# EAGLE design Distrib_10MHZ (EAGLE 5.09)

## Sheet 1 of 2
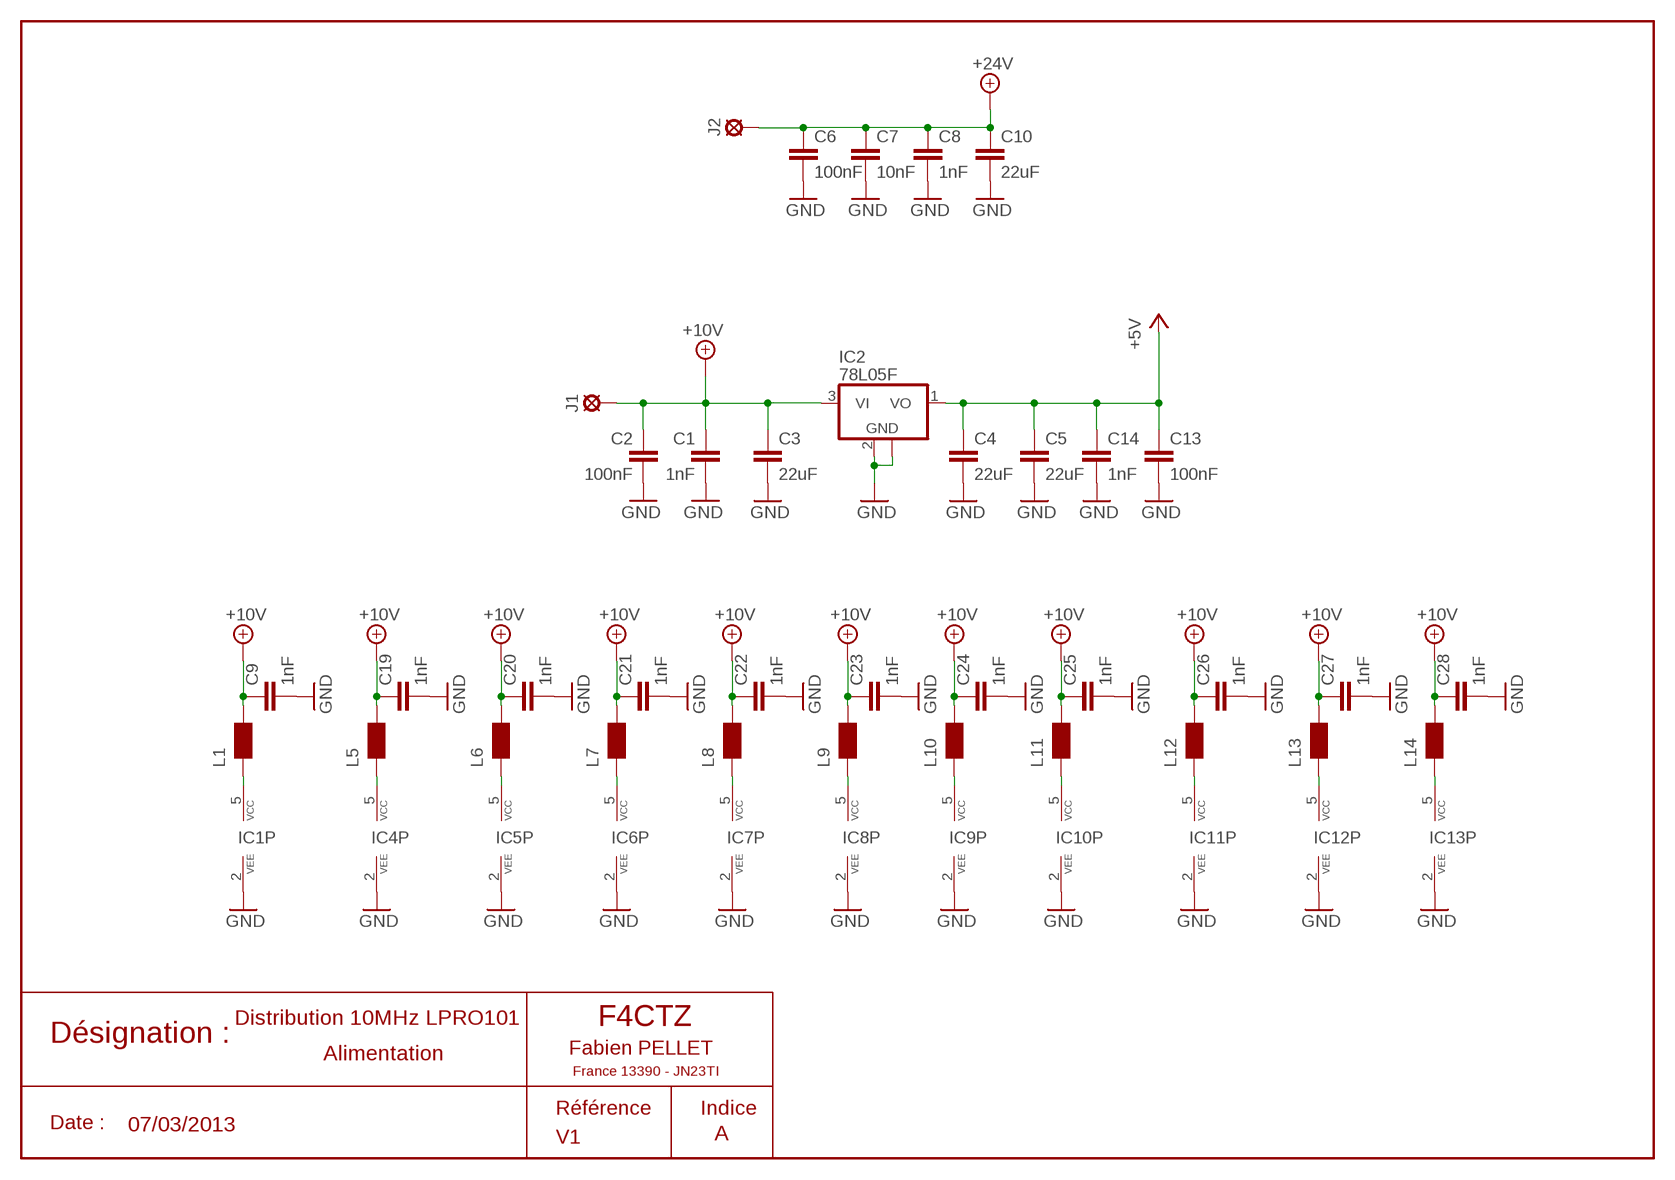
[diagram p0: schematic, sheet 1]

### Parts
C1  1nF  C-EUC0603  [C0603]
C2  100nF  C-EUC0603  [C0603]
C3  22uF  C-EUC1210  [C1210]
C4  22uF  C-EUC1210  [C1210]
C5  22uF  C-EUC1210  [C1210]
C6  100nF  C-EUC0603  [C0603]
C7  10nF  C-EUC0603  [C0603]
C8  1nF  C-EUC0603  [C0603]
C9  1nF  C-EUC0603  [C0603]
C10  22uF  C-EUC1210  [C1210]
C13  100nF  C-EUC0603  [C0603]
C14  1nF  C-EUC0603  [C0603]
C19  1nF  C-EUC0603  [C0603]
C20  1nF  C-EUC0603  [C0603]
C21  1nF  C-EUC0603  [C0603]
C22  1nF  C-EUC0603  [C0603]
C23  1nF  C-EUC0603  [C0603]
C24  1nF  C-EUC0603  [C0603]
C25  1nF  C-EUC0603  [C0603]
C26  1nF  C-EUC0603  [C0603]
C27  1nF  C-EUC0603  [C0603]
C28  1nF  C-EUC0603  [C0603]
IC1  MAX4390  MAX4105EUK  [SOT23-5L]
IC2  78L05F  [SOT89]
IC4  MAX4390  MAX4105EUK  [SOT23-5L]
IC5  MAX4390  MAX4105EUK  [SOT23-5L]
IC6  MAX4390  MAX4105EUK  [SOT23-5L]
IC7  MAX4390  MAX4105EUK  [SOT23-5L]
IC8  MAX4390  MAX4105EUK  [SOT23-5L]
IC9  MAX4390  MAX4105EUK  [SOT23-5L]
IC10  MAX4390  MAX4105EUK  [SOT23-5L]
IC11  MAX4390  MAX4105EUK  [SOT23-5L]
IC12  MAX4390  MAX4105EUK  [SOT23-5L]
IC13  MAX4390  MAX4105EUK  [SOT23-5L]
J1  +10V  SE14  [SE14]
J2  +24V  SE14  [SE14]
L1  WE-KIHC_0603  [WE-KI_0603_B]
L5  WE-KIHC_0603  [WE-KI_0603_B]
L6  WE-KIHC_0603  [WE-KI_0603_B]
L7  WE-KIHC_0603  [WE-KI_0603_B]
L8  WE-KIHC_0603  [WE-KI_0603_B]
L9  WE-KIHC_0603  [WE-KI_0603_B]
L10  WE-KIHC_0603  [WE-KI_0603_B]
L11  WE-KIHC_0603  [WE-KI_0603_B]
L12  WE-KIHC_0603  [WE-KI_0603_B]
L13  WE-KIHC_0603  [WE-KI_0603_B]
L14  WE-KIHC_0603  [WE-KI_0603_B]

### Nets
+5V: C4.1 C5.1 C13.1 C14.1 IC2.1(VO) ; also sheet 2
+10V [Alim]: C1.1 C2.1 C3.1 C9.1 C19.1 C20.1 C21.1 C22.1 C23.1 C24.1 C25.1 C26.1 C27.1 C28.1 IC2.3(VI) J1.MP L1.1 L5.1 L6.1 L7.1 L8.1 L9.1 L10.1 L11.1 L12.1 L13.1 L14.1 ; also sheet 2
+24V: C6.1 C7.1 C8.1 C10.1 J2.MP ; also sheet 2
GND [Alim]: C1.2 C2.2 C3.2 C4.2 C5.2 C6.2 C7.2 C8.2 C9.2 C10.2 C13.2 C14.2 C19.2 C20.2 C21.2 C22.2 C23.2 C24.2 C25.2 C26.2 C27.2 C28.2 IC1.2(VEE) IC2.2(GND) IC2.2@1(GND) IC4.2(VEE) IC5.2(VEE) IC6.2(VEE) IC7.2(VEE) IC8.2(VEE) IC9.2(VEE) IC10.2(VEE) IC11.2(VEE) IC12.2(VEE) IC13.2(VEE) ; also sheet 2
N$5: IC1.5(VCC) L1.2
N$15: IC4.5(VCC) L5.2
N$17: IC5.5(VCC) L6.2
N$18: IC6.5(VCC) L7.2
N$19: IC7.5(VCC) L8.2
N$20: IC8.5(VCC) L9.2
N$21: IC9.5(VCC) L10.2
N$22: IC10.5(VCC) L11.2
N$23: IC11.5(VCC) L12.2
N$24: IC12.5(VCC) L13.2
N$25: IC13.5(VCC) L14.2

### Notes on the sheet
- Distribution 10MHz LPRO101
- Alimentation
- 07/03/2013
- A

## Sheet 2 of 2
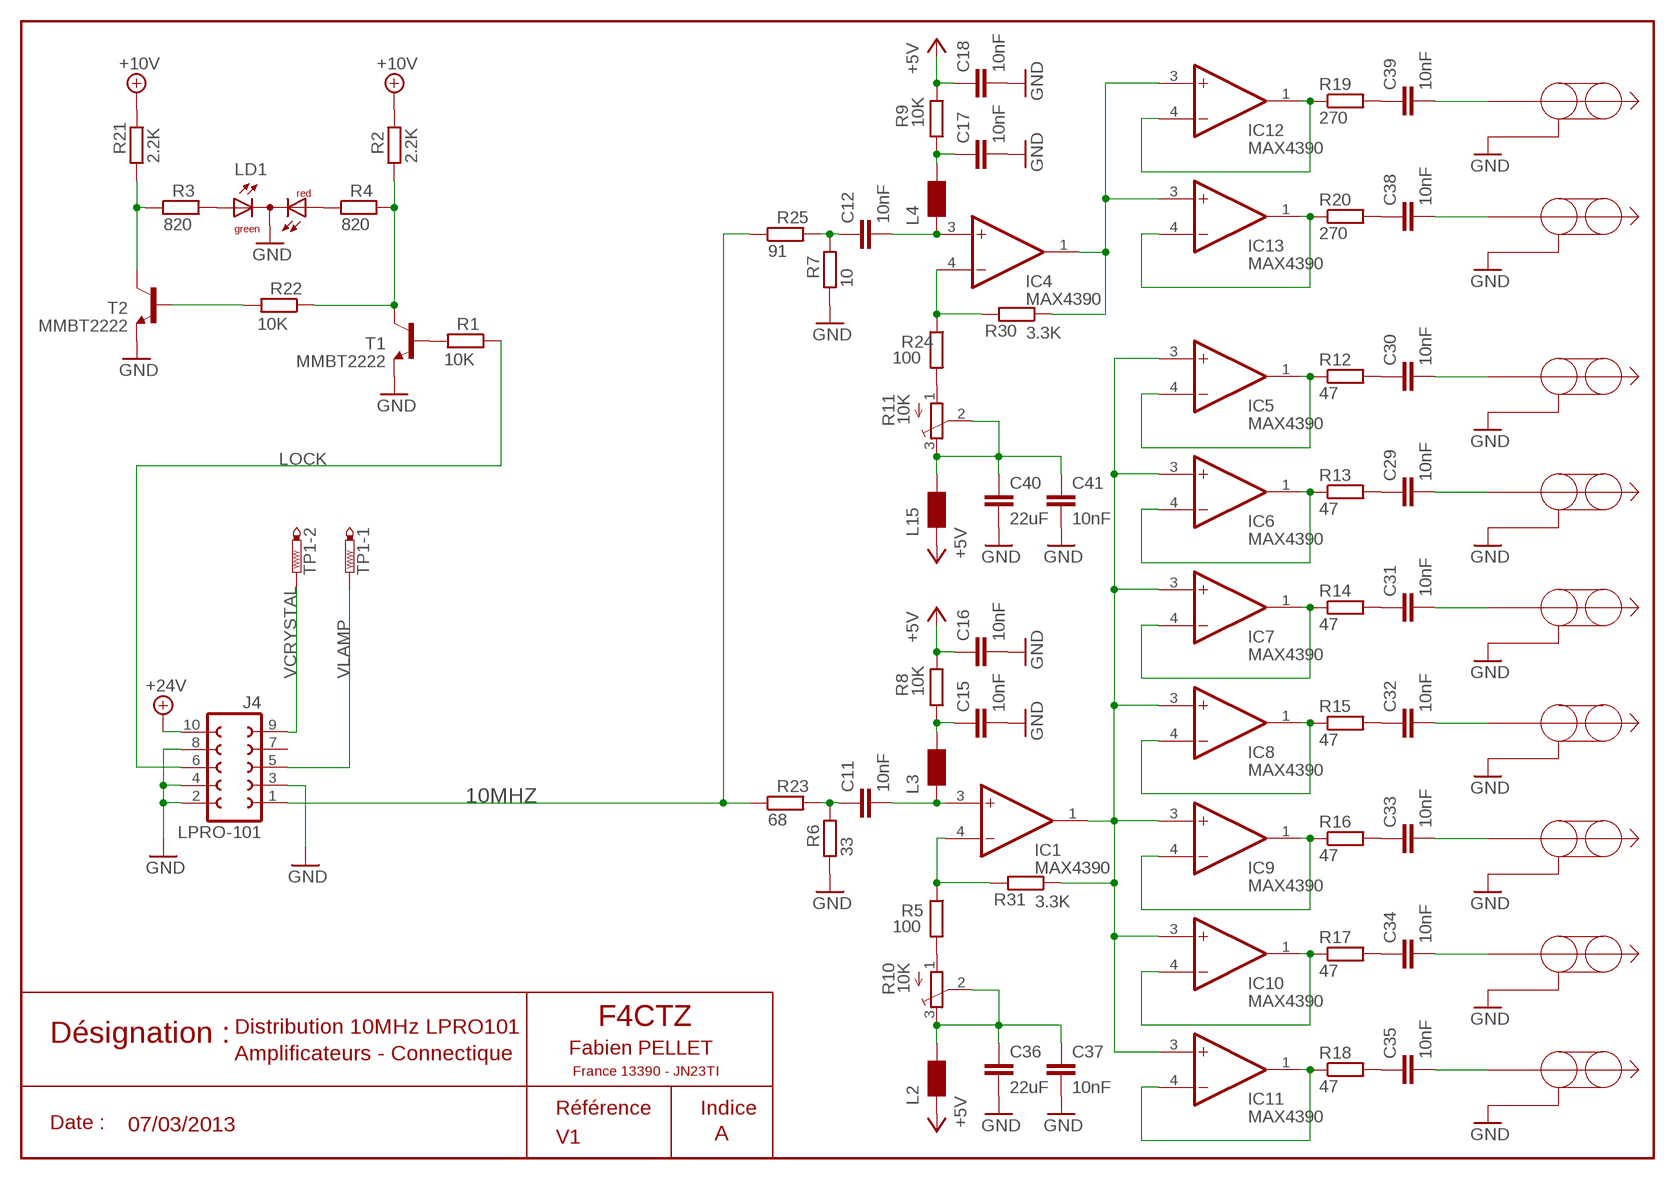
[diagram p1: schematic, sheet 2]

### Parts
C11  10nF  C-EUC0603  [C0603]
C12  10nF  C-EUC0603  [C0603]
C15  10nF  C-EUC0603  [C0603]
C16  10nF  C-EUC0603  [C0603]
C17  10nF  C-EUC0603  [C0603]
C18  10nF  C-EUC0603  [C0603]
C29  10nF  C-EUC0603  [C0603]
C30  10nF  C-EUC0603  [C0603]
C31  10nF  C-EUC0603  [C0603]
C32  10nF  C-EUC0603  [C0603]
C33  10nF  C-EUC0603  [C0603]
C34  10nF  C-EUC0603  [C0603]
C35  10nF  C-EUC0603  [C0603]
C36  22uF  C-EUC1210  [C1210]
C37  10nF  C-EUC0603  [C0603]
C38  10nF  C-EUC0603  [C0603]
C39  10nF  C-EUC0603  [C0603]
C40  22uF  C-EUC1210  [C1210]
C41  10nF  C-EUC0603  [C0603]
J4  LPRO-101  FE05-2  [FE05-2]
J5  ANT'  [ANT]
J6  ANT'  [ANT]
J7  ANT'  [ANT]
J8  ANT'  [ANT]
J9  ANT'  [ANT]
J10  ANT'  [ANT]
J11  ANT'  [ANT]
J12  ANT'  [ANT]
J13  ANT'  [ANT]
L2  WE-KIHC_0603  [WE-KI_0603_B]
L3  WE-KIHC_0603  [WE-KI_0603_B]
L4  WE-KIHC_0603  [WE-KI_0603_B]
L15  WE-KIHC_0603  [WE-KI_0603_B]
LD1  DUOLED-RG-C  [DUOLED-C-5MM]
R1  10K  R-EU_R0603  [R0603]
R2  2.2K  R-EU_R0603  [R0603]
R3  820  R-EU_R0603  [R0603]
R4  820  R-EU_R0603  [R0603]
R5  100  R-EU_R0603  [R0603]
R6  33  R-EU_R0603  [R0603]
R7  10  R-EU_R0603  [R0603]
R8  10K  R-EU_R0603  [R0603]
R9  10K  R-EU_R0603  [R0603]
R10  10K  TRIM_EU-SM-42/43W  [SM-42/43W]
R11  10K  TRIM_EU-SM-42/43W  [SM-42/43W]
R12  47  R-EU_R0603  [R0603]
R13  47  R-EU_R0603  [R0603]
R14  47  R-EU_R0603  [R0603]
R15  47  R-EU_R0603  [R0603]
R16  47  R-EU_R0603  [R0603]
R17  47  R-EU_R0603  [R0603]
R18  47  R-EU_R0603  [R0603]
R19  270  R-EU_R0603  [R0603]
R20  270  R-EU_R0603  [R0603]
R21  2.2K  R-EU_R0603  [R0603]
R22  10K  R-EU_R0603  [R0603]
R23  68  R-EU_R0603  [R0603]
R24  100  R-EU_R0603  [R0603]
R25  91  R-EU_R0603  [R0603]
R30  3.3K  R-EU_R0603  [R0603]
R31  3.3K  R-EU_R0603  [R0603]
T1  MMBT2222  MMBT2222ALT1-NPN-SOT23-BEC  [SOT23-BEC]
T2  MMBT2222  MMBT2222ALT1-NPN-SOT23-BEC  [SOT23-BEC]
TP1  PTR2  [P2-38-17]

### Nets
10MHZ [RF]: J4.1 R23.1 R25.1
+5V: C16.1 C18.1 L2.2 L15.2 R8.2 R9.2 ; also sheet 1
+10V [Alim]: R2.2 R21.2 ; also sheet 1
+24V: J4.10 ; also sheet 1
GND [Alim]: C15.2 C16.2 C17.2 C18.2 C36.2 C37.2 C40.2 C41.2 J4.2 J4.3 J4.4 J4.8 J5.P$2 J6.P$2 J7.P$2 J8.P$2 J9.P$2 J10.P$2 J11.P$2 J12.P$2 J13.P$2 LD1.C R6.1 R7.1 T1.E T2.E ; also sheet 1
LOCK: J4.6 R1.1
N$2: R2.1 R4.2 R22.1 T1.C
N$3: R1.2 T1.B
N$4: C15.1 L3.1 R8.1
N$6: R3.1 R21.1 T2.C
N$7: R22.2 T2.B
N$9: IC5.1(OUT) IC5.4(-IN) R12.1
N$10: C11.2 IC1.3(+IN) L3.2
N$11: C17.1 L4.1 R9.1
N$12: C12.2 IC4.3(+IN) L4.2
N$13: IC1.4(-IN) R5.1 R31.2
N$14 [RFOUT]: C30.2 J7.P$1
N$16 [RFOUT]: C29.2 J8.P$1
N$26: IC6.1(OUT) IC6.4(-IN) R13.1
N$27 [RFOUT]: C31.2 J9.P$1
N$28: IC7.1(OUT) IC7.4(-IN) R14.1
N$29 [RFOUT]: C32.2 J10.P$1
N$30: IC8.1(OUT) IC8.4(-IN) R15.1
N$31 [RFOUT]: C33.2 J11.P$1
N$32: IC9.1(OUT) IC9.4(-IN) R16.1
N$33 [RFOUT]: C34.2 J12.P$1
N$34: IC10.1(OUT) IC10.4(-IN) R17.1
N$35 [RFOUT]: C35.2 J13.P$1
N$36: IC11.1(OUT) IC11.4(-IN) R18.1
N$37 [RFOUT]: C39.2 J5.P$1
N$38: IC12.1(OUT) IC12.4(-IN) R19.1
N$39 [RFOUT]: C38.2 J6.P$1
N$40: IC13.1(OUT) IC13.4(-IN) R20.1
N$41: LD1.AX(AG) R3.2
N$42: IC4.1(OUT) IC12.3(+IN) IC13.3(+IN) R30.1
N$43: IC1.1(OUT) IC5.3(+IN) IC6.3(+IN) IC7.3(+IN) IC8.3(+IN) IC9.3(+IN) IC10.3(+IN) IC11.3(+IN) R31.1
N$44: LD1.AR R4.1
N$45: IC4.4(-IN) R24.1 R30.2
N$46: C12.1 R7.2 R25.2
N$47: C29.1 R13.2
N$48: C30.1 R12.2
N$49: C31.1 R14.2
N$50: C32.1 R15.2
N$51: C33.1 R16.2
N$52: C34.1 R17.2
N$53: C35.1 R18.2
N$54: C36.1 C37.1 L2.1 R10.2(S) R10.3(E)
N$55: R5.2 R10.1(A)
N$56: C39.1 R19.2
N$57: C38.1 R20.2
N$58: C40.1 C41.1 L15.1 R11.2(S) R11.3(E)
N$59: R11.1(A) R24.2
N$60: C11.1 R6.2 R23.2
VCRYSTAL: J4.9 TP1.TP-2
VLAMP: J4.5 TP1.TP-1
Unconnected: J4.7

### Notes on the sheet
- Distribution 10MHz LPRO101
- Amplificateurs - Connectique
- 07/03/2013
- A

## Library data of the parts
C1-C41 = rcl:C-EU: CAPACITOR, European symbol
IC1 IC4-IC13 = maxim:MAX4105EUK: OP AMP
IC2 = linear:78L*: POSITOIV-VOLTAGE REGULATORS Output up to 100 mA Source: http://focus.ti.com/lit/ds/symlink/ua78l05.pdf
J1 J2 = solpad:SE14: SOLDER PAD
J4 = con-lsta:FE05-2: FEMALE HEADER
J5-J13 = fabien:ANT
L1-L15 = wuerth-elektronik:WE-KIHC: SMD Wire Wound Ceramic Inductor WE-KIHC
LD1 = led:DUOLED-RG-C: DUO LED 2 colors (red/green), 5 mm, round, common Cathode www.ligitek.com or other producers.
R1-R9 R12-R25 R30 R31 = rcl:R-EU_: RESISTOR, European symbol
R10 R11 = pot:TRIM_EU-: POTENTIOMETER
T1 T2 = transistor-neu-to92:*-NPN-: NPN Transistror
TP1 = testpad:PTR2: TEST PIN

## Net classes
1 Alim: clearance 0.4 mm to class 0, clearance 0.4 mm
2 RF: clearance 1.5 mm to class 0, clearance 1.5 mm to class 1, clearance 1.5 mm
3 RFOUT: clearance 1 mm to class 0, clearance 1 mm to class 1, clearance 1 mm to class 2, clearance 1 mm

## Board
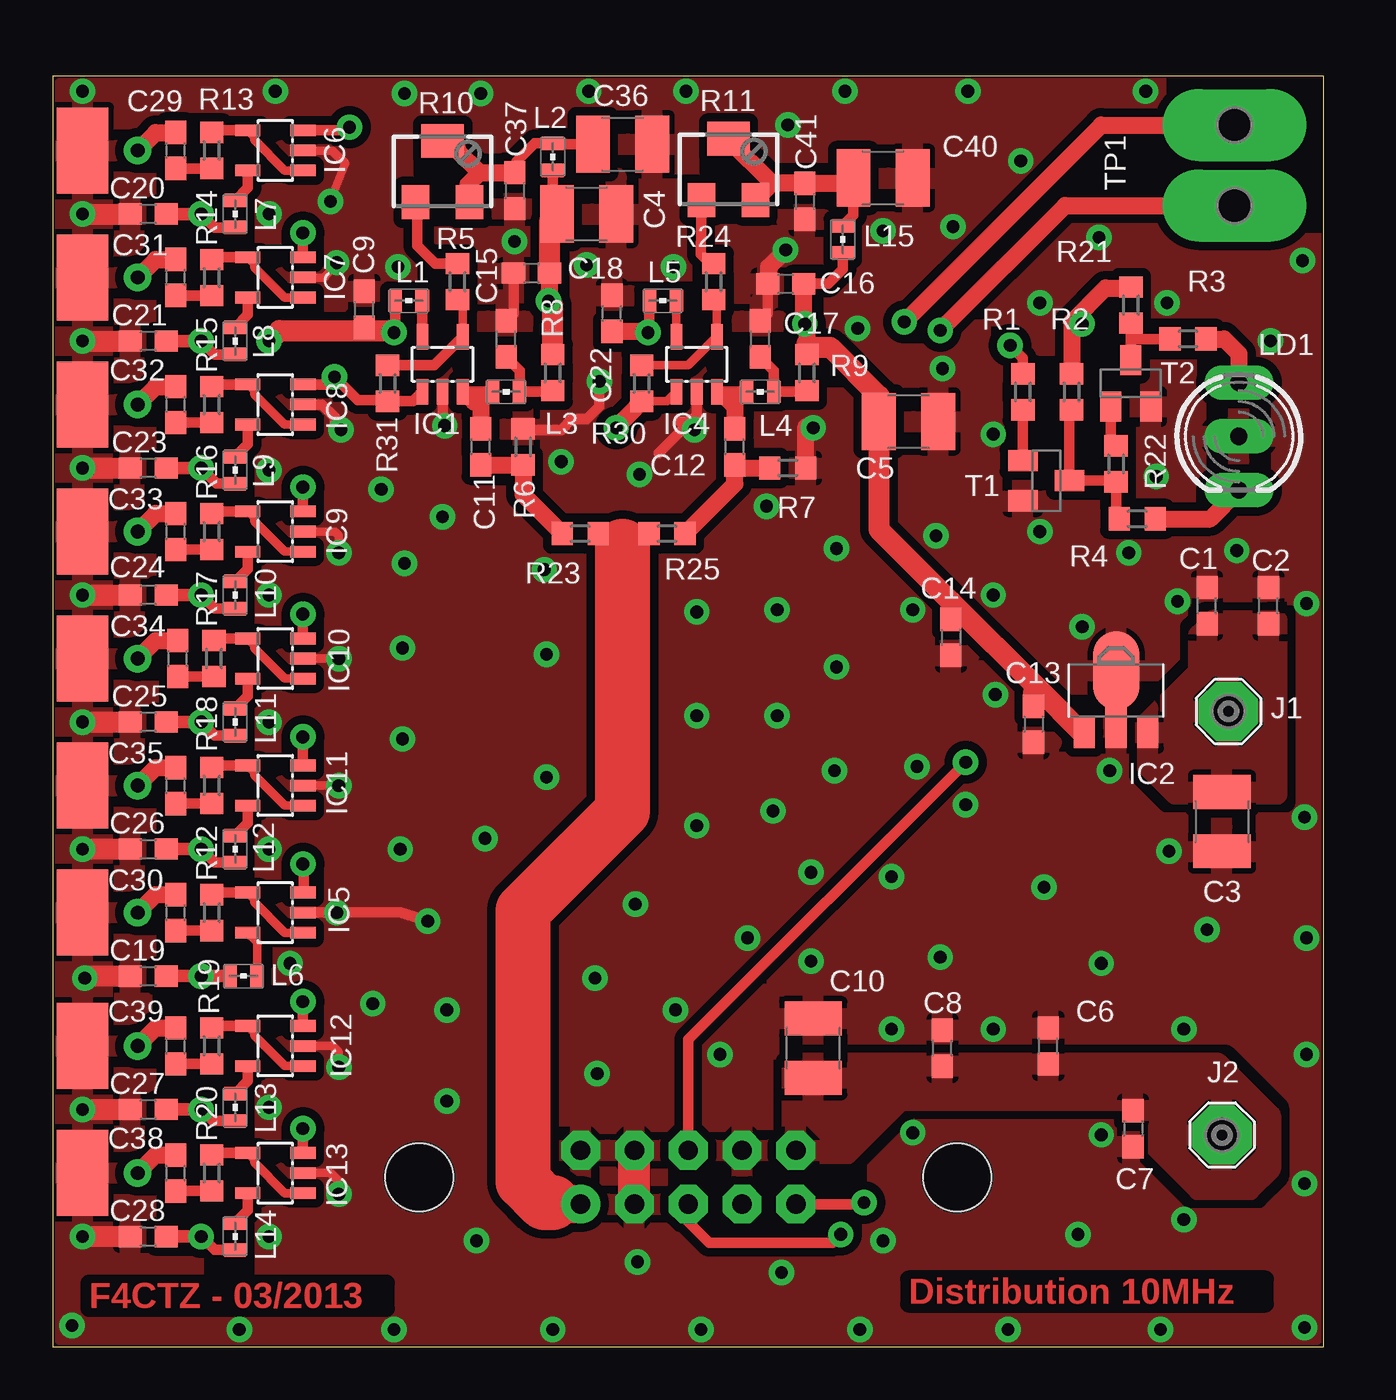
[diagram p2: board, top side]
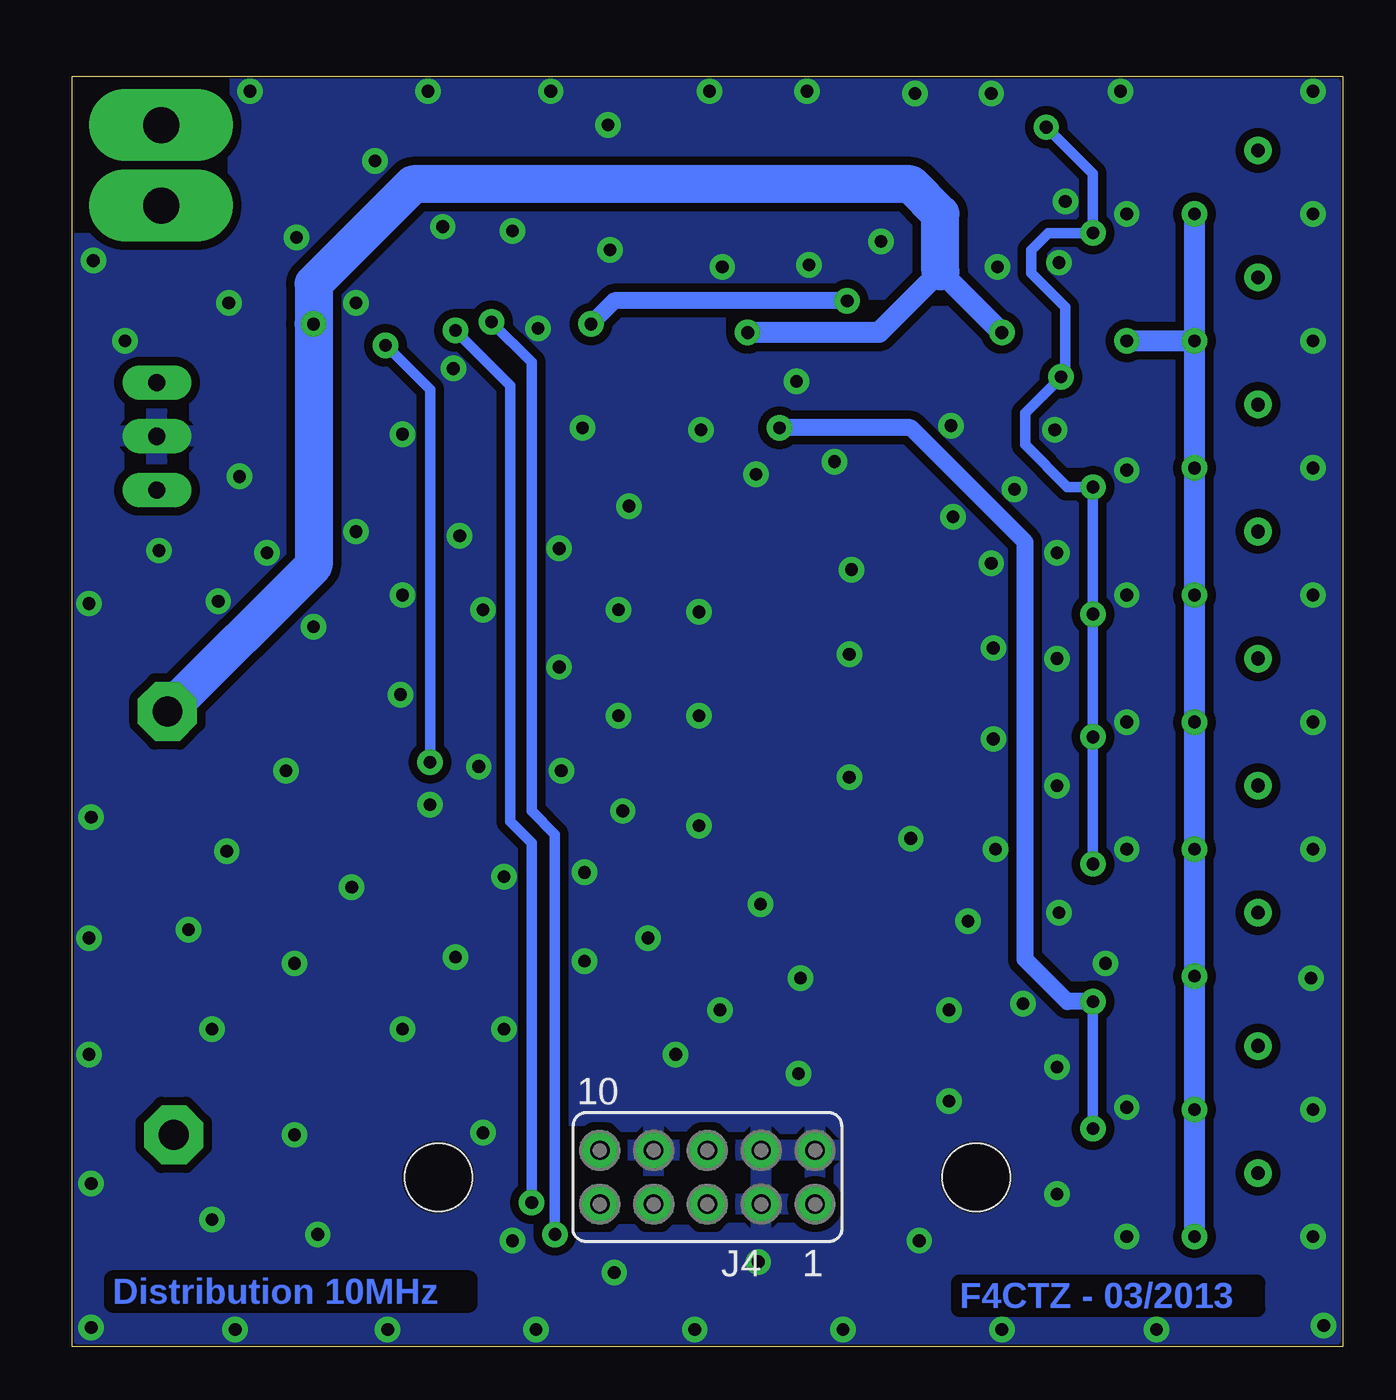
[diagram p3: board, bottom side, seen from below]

Size 60 x 60 mm. Coordinates in mm from the lower left corner, seen from the top.
Outline: 0,0 60,0 60,60 0,60 0,0
Copper layers (1*16): Top 0.035mm / dielectric 1.53mm / Bottom 0.035mm
Design rules "fabien *": minimum track width 0.21mm, minimum drill 0.5mm, track to track 0.21mm, track to pad 0.21mm, pad to pad 0.21mm, via to via 0.21mm, smd to smd 0.21mm, copper to edge 0.1mm, drill to drill 8mil, minimum pad ring 0.2mm, minimum via ring 0.2mm, stop-mask expansion 4mil, vias tented up to drill 0mil, thermal gap 10mil
Holes 3.2 mm at 17.3,8 42.7,8

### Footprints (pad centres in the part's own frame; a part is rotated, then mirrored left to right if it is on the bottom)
C0603 = smd 1.1 x 1: 1 -0.85,0; 2 0.85,0
C1210 = smd 1.6 x 2.7: 1 -1.4,0; 2 1.4,0
SOT23-5L = smd 0.55 x 1.2: 1 -0.95,-1.3; 2 0,-1.3; 3 0.95,-1.3; 4 0.95,1.3; 5 -0.95,1.3
SOT89 = smd 1 x 1.5: 1 -1.499,-1.981; 3 1.499,-1.981 | smd 1 x 2: 2 0,-1.727 | smd 2.2 x 3.7: 2@1 0,0.94
SE14 = drill 1.397 pad 2.54 octagon: MP 0,0
FE05-2 = drill 0.914 round: 1 -5.08,1.27 | drill 0.914 octagon: 2 -5.08,-1.27; 3 -2.54,1.27; 4 -2.54,-1.27; 5 0,1.27; 6 0,-1.27; 7 2.54,1.27; 8 2.54,-1.27; 9 5.08,1.27; 10 5.08,-1.27
ANT = drill 0.65 pad 1.032 round: P$1 0,0 | smd 4.064 x 2.438: P$2 0,-2.601
WE-KI_0603_B = smd 0.64 x 1.02: 1 -0.64,0; 2 0.64,0
DUOLED-C-5MM = drill 0.813 long: AR 2.54,0; AX -2.54,0; C 0,0
R0603 = smd 1 x 1.1: 1 -0.85,0; 2 0.85,0
SM-42/43W = smd 1.3 x 1.6: 1 -1.27,-1.45; 3 1.27,-1.45 | smd 2 x 1.6: 2 0,1.45
SOT23-BEC = smd 1 x 1.4: B -0.95,-1.1; C 0,1.1; E 0.95,-1.1
P2-38-17 = drill 1.702 pad 2.121 long: TP-1 -1.905,0; TP-2 1.905,0

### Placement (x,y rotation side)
C1  54.5,35 90 top
C2  57.4,35 90 top
C3  55.2,24.8 270 top
C4  25.2,53.5 0 top
C5  40.4,43.7 0 top
C6  47,14.2 90 top
C7  51,10.3 270 top
C8  42,14.1 90 top
C9  14.7,49 90 top
C10  35.9,14.1 90 top
C11  20.2,42.5 90 top
C12  32.2,42.5 90 top
C13  46.3,29.4 270 top
C14  42.4,33.5 270 top
C15  21.4,47.6 90 top
C16  34.6,50.2 180 top
C17  33.4,47.6 90 top
C18  22.6,50.7 180 top
C19  4.5,17.5 180 top
C20  4.5,53.5 180 top
C21  4.5,47.5 180 top
C22  26.4,48.8 90 top
C23  4.5,41.5 180 top
C24  4.5,35.5 180 top
C25  4.5,29.5 180 top
C26  4.5,23.5 180 top
C27  4.5,11.2 180 top
C28  4.5,5.2 180 top
C29  5.8,56.5 90 top
C30  5.8,20.5 90 top
C31  5.8,50.5 90 top
C32  5.8,44.5 90 top
C33  5.8,38.5 90 top
C34  5.9,32.5 90 top
C35  5.8,26.5 90 top
C36  26.9,56.8 0 top
C37  21.8,54.6 270 top
C38  5.8,8.2 90 top
C39  5.8,14.2 90 top
C40  39.2,55.2 0 top
C41  35.5,54.1 270 top
IC1  18.4,46.4 0 top
IC2  50.2,31 0 top
IC4  30.4,46.4 0 top
IC5  10.5,20.5 90 top
IC6  10.5,56.5 90 top
IC7  10.5,50.5 90 top
IC8  10.5,44.5 90 top
IC9  10.5,38.5 90 top
IC10  10.5,32.5 90 top
IC11  10.5,26.5 90 top
IC12  10.5,14.2 90 top
IC13  10.5,8.2 90 top
J1  55.5,30 0 top
J2  55.2,10 0 top
J4  30,8 180 bottom
J5  4,14.2 270 top
J6  4,8.2 270 top
J7  4,20.5 270 top
J8  4,56.5 270 top
J9  4,50.5 270 top
J10  4,44.5 270 top
J11  4,38.5 270 top
J12  4,32.5 270 top
J13  4,26.5 270 top
L1  16.8,49.4 0 top
L2  23.6,56.2 270 top
L3  21.4,45.1 180 top
L4  33.4,45.1 180 top
L5  28.8,49.4 0 top
L6  9,17.5 0 top
L7  8.6,53.5 90 top
L8  8.6,47.5 90 top
L9  8.6,41.4 90 top
L10  8.6,35.5 90 top
L11  8.6,29.5 90 top
L12  8.6,23.5 90 top
L13  8.6,11.3 90 top
L14  8.6,5.2 90 top
L15  37.3,52.3 270 top
LD1  56,43 270 top
R1  45.8,45.1 270 top
R2  48.1,45.1 90 top
R3  53.6,47.6 0 top
R4  51.2,39.1 180 top
R5  19.1,50.3 90 top
R6  22.2,42.5 270 top
R7  34.7,41.5 180 top
R8  23.6,46 90 top
R9  35.6,46 90 top
R10  18.4,55.5 0 top
R11  31.9,55.6 0 top
R12  7.5,20.5 270 top
R13  7.5,56.5 270 top
R14  7.5,50.5 270 top
R15  7.5,44.5 270 top
R16  7.5,38.5 270 top
R17  7.6,32.5 270 top
R18  7.5,26.5 270 top
R19  7.5,14.2 270 top
R20  7.5,8.2 270 top
R21  50.9,49.2 90 top
R22  50.2,41.7 90 top
R23  24.9,38.4 180 top
R24  31.2,50.3 90 top
R25  29,38.4 0 top
R30  27.8,45.5 90 top
R31  15.8,45.5 90 top
T1  46.9,40.9 270 top
T2  50.9,45.5 0 top
TP1  55.8,55.8 270 top

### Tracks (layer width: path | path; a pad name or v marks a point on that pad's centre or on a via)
10MHZ
  Top 0.8: R23.1 26.35,37.8 26.9,37.8 27.5,38.4 R25.1
  Top 1.8: J4.1 23.67,6.73 23.6,6.8
  Top 2.6: 23.6,6.8 23.2,6.8 22.2,7.8 22.2,20.6 26.9,25.3 26.9,37.8
+5V  (via drill 0.6)
  Top 0.5: 23.45,49.45 23.45,49.35 23.6,49.2 | L2.2 23.6,53.7 C4.1 | C16.1 36.6,50.2 37.3,50.9 L15.2
  Top 0.8: R9.2 35.6,47.4 35.6,48.2 v35.5,48.3 35.45,48.35 C16.1 | C18.1 23.45,49.45 v23.4,49.4
  Top 1: IC2.1 48.58,29.02 46.5,31.1 | 42.4,35.2 46.5,31.1 | 35.6,47.4 35.8,47.2 36.7,47.2 39,44.9 C5.1 39,38.6 42.4,35.2 | 42.4,35.2 C14.1 | C13.1 46.3,30.9 46.5,31.1 | C18.1 23.45,53.15 C4.1 | R8.2 23.6,49.2 v23.4,49.4
  Bottom 0.8: v23.4,49.4 34.4,49.4 v35.5,48.3
+10V  (via drill 0.6)
  Top 0.5: L5.1 28.16,47.96 v28.1,47.9 | L1.1 16.16,47.96 v16.1,47.9 | L7.1 7.64,52.86 v7,53.5 | L14.1 7.64,4.56 v7,5.2 | L13.1 7.54,10.66 v7,11.2 | L12.1 7.64,22.86 v7,23.5 | L11.1 7.64,28.86 v7,29.5 | L10.1 7.64,34.86 v7,35.5 | L9.1 7.74,40.76 v7,41.5 | L8.1 7.64,46.86 v7,47.5 | C9.1 14.5,48.1 14.6,48 | 15.9,48 16.1,48
  Top 0.6: v7,53.5 C20.1 | v7,47.5 C21.1 | C28.1 v7,5.2 | v7,11.2 C27.1 | v7,23.5 C26.1 | v7,29.5 C25.1 | v7,35.5 C24.1 | v7,41.5 C23.1 | L6.1 v7,17.5 C19.1
  Top 0.8: C22.1 28.05,47.95 v28.1,47.9 | 16.1,48 v16.1,47.9 | 48.1,48.4 R2.2 | 48.1,48.4 49.7,50 50.85,50 R21.2 | 48.1,48.4 48.5,48.4 v48.6,48.3
  Top 1: 15.9,48 14.6,48 10.7,48 v10.2,47.5
  Bottom 1: v7,47.5 v7,53.5 | v7,47.5 v7,41.5 v7,35.5 v7,29.5 v7,23.5 v7,17.5 v7,11.2 v7,5.2 | v7,47.5 v10.2,47.5 | v16.1,47.9 19,50.8 21.9,47.9 v28.1,47.9
  Bottom 1.8: J1.MP 48.6,36.9 v48.6,48.3 48.6,50.2 43.9,54.9 20.4,54.9 19,53.5 19,50.8
  pour Top: 57.8,34.3 57.8,26.1 53,26.1 51.6,27.5 51.6,29.4 54.1,31.9 54.1,33.6 54.8,34.3
+24V
  pour Top: 34.9,9.1 34.9,13.4 55,13.4 57.5,10.9 57.5,8.4 56.5,7.4 54.1,7.4 52.1,9.4 52.1,10.8 51.3,11.6 40,11.6 37.5,9.1
GND  (via drill 0.6)
  Top 0.4: IC6.2 13.2,56.5 13.8,55.9 v13.1,54.1 | IC13.2 13.1,8.2 13.5,7.8 v13.5,7.2 | IC11.2 13.1,26.5 13.5,26.1 v13.5,26.5 | IC12.2 13.2,14.2 13.5,13.9 v13.5,13.2 | IC10.2 13.1,32.5 13.5,32.1 v13.5,32.5 | IC9.2 13.3,38.5 13.5,38.3 v13.5,37.5 | IC7.2 12.8,50.5 v13.4,51.2
  Top 0.5: C16.2 33.75,48.8 C17.2 | C18.2 21.75,48.8 C15.2 | R6.1 22.25,43.3 24,43.3 24.5,43.8 25.2,43.8 25.8,44.4 v25.8,45.6 | IC4.2 30.4,44 30.1,43.7 | 28.6,42.2 30.1,43.7 | IC1.2 18.4,43.6 v18.5,43.5 | IC5.2 16.4,20.5 v17.7,20.1 | 30.1,43.7 29.6,43.7 v30.3,43.3 | IC8.2 12.7,44.5 13.3,43.9 13.3,43.6 v13.6,43.3
  Top 0.8: R7.1 35.55,43.45 v35.9,43.4 | v34.6,51.8 33.8,51 33.8,50.25 C16.2
  Top 1: v1.4,5.2 C28.2 | v1.4,11.2 C27.2 | v1.4,23.5 C26.2 | v1.4,29.5 C25.2 | v1.4,35.5 C24.2 | v1.4,41.5 C23.2 | v1.4,47.5 C21.2 | v1.4,53.5 C20.2 | C19.2 1.6,17.5 v1.5,17.4
  Top 1.5: J4.3 J4.4
  other vias: 10.2,53.5 1.4,59.3 10.5,59.3 10.2,41.4 10.2,35.5 10.2,29.5 10.2,23.5 10.2,11.3 10.2,5.2 25.2,51.1 24,41.8 15.5,40.5 18.4,39.2 23.2,36.7 23.3,26.9 16.6,37 20.4,24 18.6,15.9 20,5 25.6,17.4 25.7,12.9 38.1,0.8 30.6,0.8 23.6,0.8 16.1,0.8 8.8,0.8 0.9,1 45.1,0.8 52.3,0.8 59.1,0.9 23.3,32.7 16.5,33 16.4,23.5 16.5,28.7 37,37.7 37,32.1 36.9,27.2 34.2,34.8 30.4,34.7 34.2,29.8 34,25.3 30.4,29.8 30.4,24.6 27.5,20.9 29.4,15.9 13.4,20.5 11.2,18.1 15.1,16.2 18.6,11.6 27.6,4 34.4,3.5 39.2,5 31.5,13.8 35.8,18.2 35.8,22.4 32.8,19.3 33.7,39.7 21.8,52.2 49.5,10 40.6,10.1 48.4,5.3 53.4,6 59.1,7.7 59.2,13.8 53.4,15 44.4,15 39.6,15 39.6,22.2 44.5,30.8 40.8,27.4 49.9,27.2 43.1,25.6 41.9,18.4 46.8,21.7 49.5,18.1 52.7,23.4 54.5,19.7 59.1,25 40.6,34.8 50.8,37.5 53.1,35.2 55.9,37.6 59.2,35.1 52.1,41.1 44.4,35.5 48.6,34 46.6,38.5 44.4,43.1 41.7,38.3 42,46.2 46.6,49.3 38,48.1 39.2,52.7 42.5,52.9 49.4,52.4 52.6,49.3 59,51.3 57.5,47.5 59.2,19.3 45.7,56 51.6,59.3 43.2,59.3 34.7,57.7 29.3,51 29.9,59.3 37.4,59.3 25.3,59.3 20.2,59.2 16.6,59.2 16.3,51 27.7,41.2
  pour Top (rank 6): 0.5,0.5 59.5,0.5 59.5,59.5 0.5,59.5
  pour Bottom (rank 6): 0.5,0.5 59.5,0.5 59.5,59.5 0.5,59.5
LOCK  (via drill 0.6)
  Top 0.5: 45.75,46 R1.1 45.8,46.7 v45.2,47.3 | J4.6 30,14.5 v43.1,27.6
  Bottom 0.5: v43.1,27.6 43.1,45.2 v45.2,47.3
N$2
  Top 0.5: 48,44.1 T1.C 50.15,40.9 R22.1 50.2,39.25 R4.2 | 48,44.1 48,44.15 | R2.1 48.1,44.2 48,44.1
N$3
  Top 0.5: T1.B R1.2
N$4
  Top 0.5: C15.1 22.04,46.11 L3.1 23.55,45.1 R8.1
N$5
  Top 0.5: IC1.5 L1.2
N$6
  Top 0.5: 50.9,47.5 T2.C | 50.9,47.5 R21.1 | R3.1 51,47.6 50.9,47.5
N$7
  Top 0.5: T2.B 49.95,42.8 R22.2
N$9
  Top 0.4: IC5.1 10.95,19.55 9.5,21 9.5,21.15 IC5.4
  Top 0.5: IC5.4 7.6,21.45 R12.1
N$10
  Top 0.5: IC1.3 19.9,45.1 | 19.9,45.1 L3.2 | 19.8,44.7 19.8,45 19.9,45.1
  Top 0.8: C11.2 20.2,44.6 19.9,44.6 19.8,44.7
N$11
  Top 0.5: R9.1 35.55,45.1 L4.1 34.04,46.11 C17.1
N$12
  Top 0.5: IC4.3 31.8,45.1 | 31.8,45.1 31.8,44.8 | 31.8,45.1 L4.2
  Top 0.8: C12.2 32.2,44.6 32,44.6 31.8,44.8
N$13
  Top 0.4: IC1.4 19.35,49.2 R5.1
  Top 0.5: IC1.4 18,46.35 R31.2
N$14
  Top 0.8: C30.2 4.85,21.35 J7.P$1
N$15
  Top 0.4: L5.2 IC4.5
N$16
  Top 0.8: C29.2 4.85,57.35 J8.P$1
N$17
  Top 0.4: L6.2 9.64,19.11 IC5.5
N$18
  Top 0.5: IC6.5 9.2,54.74 L7.2
N$19
  Top 0.5: IC7.5 9.2,48.74 L8.2
N$20
  Top 0.5: IC8.5 9.2,42.64 L9.2
N$21
  Top 0.5: IC9.5 9.2,36.74 L10.2
N$22
  Top 0.5: IC10.5 9.2,30.74 L11.2
N$23
  Top 0.5: IC11.5 9.2,24.74 L12.2
N$24
  Top 0.5: IC12.5 9.2,12.54 L13.2
N$25
  Top 0.5: IC13.5 9.2,6.44 L14.2
N$26
  Top 0.4: IC6.1 10.95,55.55 9.5,57 9.5,57.15 IC6.4
  Top 0.5: IC6.4 7.6,57.45 R13.1
N$27
  Top 0.8: C31.2 4.85,51.35 J9.P$1
N$28
  Top 0.4: IC7.1 10.95,49.55 9.5,51 9.5,51.15 IC7.4
  Top 0.5: IC7.4 7.6,51.45 R14.1
N$29
  Top 0.8: C32.2 4.85,45.35 J10.P$1
N$30
  Top 0.4: IC8.1 10.95,43.55 9.5,45 9.5,45.15 IC8.4
  Top 0.5: IC8.4 7.6,45.45 R15.1
N$31
  Top 0.8: C33.2 4.85,39.35 J11.P$1
N$32
  Top 0.4: IC9.1 10.95,37.55 9.5,39 9.5,39.15 IC9.4
  Top 0.5: IC9.4 7.6,39.45 R16.1
N$33
  Top 0.8: C34.2 4.85,33.35 J12.P$1
N$34
  Top 0.4: IC10.1 10.95,31.55 9.5,33 9.5,33.15 IC10.4
  Top 0.5: IC10.4 7.7,33.45 R17.1
N$35
  Top 0.8: C35.2 4.85,27.35 J13.P$1
N$36
  Top 0.4: IC11.1 10.95,25.55 9.5,27 9.5,27.15 IC11.4
  Top 0.5: IC11.4 7.6,27.45 R18.1
N$37
  Top 0.8: C39.2 4.85,15.05 J5.P$1
N$38
  Top 0.4: IC12.1 10.95,13.25 9.5,14.7 9.5,14.85 IC12.4
  Top 0.5: IC12.4 7.6,15.15 R19.1
N$39
  Top 0.8: C38.2 4.85,9.05 J6.P$1
N$40
  Top 0.4: IC13.1 10.95,7.25 9.5,8.7 9.5,8.85 IC13.4
  Top 0.5: IC13.4 7.6,9.15 R20.1
N$41
  Top 0.8: R3.2 55.3,47.6 56,46.9 LD1.AX
N$42  (via drill 0.6)
  Top 0.4: R30.1 29,44.65 IC4.1
  Top 0.5: v11.8,16.3 IC12.3 | IC13.3 v11.8,10.3
  Top 0.8: v26.6,43.4 R30.1
  Bottom 0.5: v11.8,10.3 v11.8,16.3
  Bottom 0.8: v26.6,43.4 20.4,43.4 15,38 15,18.3 13,16.3 v11.8,16.3
N$43  (via drill 0.6)
  Top 0.5: v11.8,28.8 IC11.3 | IC6.3 13.85,57.45 v14,57.6 | v11.8,52.6 IC7.3 | v11.8,34.6 IC10.3 | v11.8,40.6 IC9.3 | IC5.3 11.85,21.5 11.85,22.75 v11.8,22.8 | IC8.3 12.95,45.45 v13.3,45.8 14.4,44.7 15.75,44.7 R31.1 17,44.65 IC1.1
  Bottom 0.5: v14,57.6 11.8,55.4 v11.8,52.6 13.9,52.6 14.7,51.8 14.7,50.7 13.1,49.1 13.1,45.7 v13.3,45.8 15,44.1 15,42.6 13,40.6 v11.8,40.6 v11.8,34.6 v11.8,28.8 v11.8,22.8
N$44
  Top 0.8: R4.1 54.64,39.1 LD1.AR
N$45
  Top 0.4: R30.2 30,46.35 IC4.4 31.35,49.3 R24.1
N$46
  Top 0.8: R7.2 32.35,41.5 C12.1 32.2,40.75 R25.2
N$47
  Top 0.5: C29.1 R13.2
N$48
  Top 0.5: C30.1 R12.2
N$49
  Top 0.5: C31.1 R14.2
N$50
  Top 0.5: C32.1 R15.2
N$51
  Top 0.5: C33.1 R16.2
N$52
  Top 0.5: C34.1 R17.2
N$53
  Top 0.5: C35.1 R18.2
N$54
  Top 0.5: C36.1 23.64,56.8 L2.1 22.74,56.84 21.9,56 21.9,55.55 C37.1
  Top 0.8: 20.15,55.45 C37.1 | 20.15,55.45 19.1,56.5 19.1,56.6 18.9,56.8 18.9,57.2 R10.2 | R10.3 19.6,54.1 19.6,54.9 20.15,55.45
N$55
  Top 0.5: R5.2 18.05,51.15 17.2,52 17.2,54 R10.1
N$56
  Top 0.5: C39.1 R19.2
N$57
  Top 0.5: C38.1 R20.2
N$58
  Top 0.5: L15.1 37.8,53.44 C40.1
  Top 0.8: C40.1 37.55,54.95 C41.1 33.97,54.95 | 33.97,54.95 R11.3 | R11.2 31.9,57.02 33.97,54.95
N$59
  Top 0.5: R24.2 31.05,51.15 30.6,51.6 R11.1
N$60
  Top 0.8: R23.2 22.2,40.25 R6.2 C11.1
VCRYSTAL  (via drill 0.6)
  Top 0.5: J4.9 38.23,6.73 v38.3,6.8 | v41.9,48 42,48.1
  Top 0.8: TP1.TP-2 47.8,53.9 42,48.1
  Bottom 0.5: v38.3,6.8 38.3,23.8 39.3,24.8 39.3,45.4 v41.9,48
VLAMP  (via drill 0.6)
  Top 0.5: J4.5 30,5.9 31,4.9 36.8,4.9 v37.2,5.3
  Top 0.8: v40.2,48.4 49.5,57.7 TP1.TP-1
  Bottom 0.5: 37.1,5.4 v37.2,5.3 37.2,24.2 38.3,25.3 38.3,46.5 v40.2,48.4

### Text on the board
Top: F4CTZ - 03/2013 | Distribution 10MHz
Bottom: F4CTZ - 03/2013 | Distribution 10MHz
